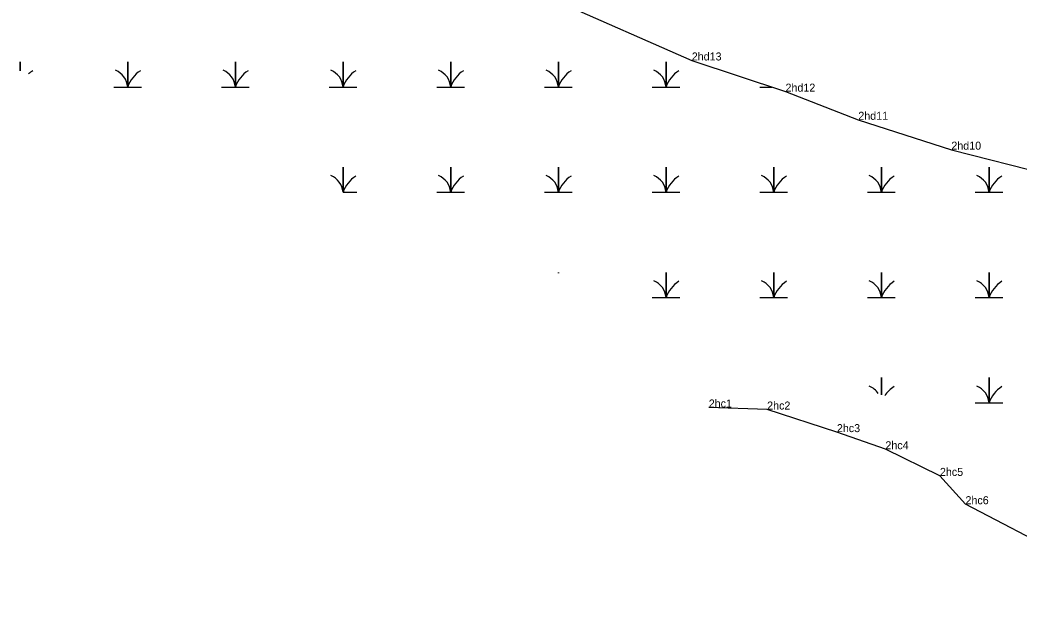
# Model space of a CAD drawing. Extents: x 2072529 to 2268796, y 436423 to 470406.
# Drawn here: x 2106175 to 2106799, y 453813 to 454182 of the extents above; entities that cross this region are included whole.
import ezdxf

# ---------------------------------------------------------------- set-up
doc = ezdxf.new("R2010")
doc.units = 0
for name, color, linetype in [('Exist Environmental Wetland Boundary Cogo Comment', 7, 'Continuous'), ('Exist Environmental Wetland Boundary Cogo Point CELL', 7, 'Continuous'), ('Old_Level_20', 7, 'Continuous')]:
    doc.layers.add(name, color=color, linetype=linetype)

msp = doc.modelspace()

# ---------------------------------------------------------------- linework, layer by layer
at = {"layer": 'Exist Environmental Wetland Boundary Cogo Point CELL'}
for points in [[(2106174.89, 454150.51), (2106174.89, 454156.11), (2106174.89, 454150.51)], [(2106233.53, 454140.33), (2106242.14, 454140.33), (2106242.14, 454156.11), (2106242.14, 454140.33), (2106250.74, 454140.33)], [(2106300.78, 454140.33), (2106309.39, 454140.33), (2106309.39, 454156.11), (2106309.39, 454140.33), (2106317.99, 454140.33)], [(2106368.03, 454140.33), (2106376.64, 454140.33), (2106376.64, 454156.11), (2106376.64, 454140.33), (2106385.24, 454140.33)], [(2106435.28, 454140.33), (2106443.89, 454140.33), (2106443.89, 454156.11), (2106443.89, 454140.33), (2106452.49, 454140.33)], [(2106502.53, 454140.33), (2106511.14, 454140.33), (2106511.14, 454156.11), (2106511.14, 454140.33), (2106519.74, 454140.33)], [(2106569.78, 454140.33), (2106578.39, 454140.33), (2106578.39, 454156.11), (2106578.39, 454140.33), (2106586.99, 454140.33)], [(2106637.03, 454140.33), (2106644.39, 454140.33)], [(2106376.64, 454074.58), (2106376.64, 454090.31), (2106376.64, 454074.58)], [(2106435.28, 454074.53), (2106443.89, 454074.53), (2106443.89, 454090.31), (2106443.89, 454074.53), (2106452.49, 454074.53)], [(2106502.53, 454074.53), (2106511.14, 454074.53), (2106511.14, 454090.31), (2106511.14, 454074.53), (2106519.74, 454074.53)], [(2106569.78, 454074.53), (2106578.39, 454074.53), (2106578.39, 454090.31), (2106578.39, 454074.53), (2106586.99, 454074.53)], [(2106637.03, 454074.53), (2106645.64, 454074.53), (2106645.64, 454090.31), (2106645.64, 454074.53), (2106654.24, 454074.53)], [(2106704.28, 454074.53), (2106712.89, 454074.53), (2106712.89, 454090.31), (2106712.89, 454074.53), (2106721.49, 454074.53)], [(2106771.53, 454074.53), (2106780.14, 454074.53), (2106780.14, 454090.31), (2106780.14, 454074.53), (2106788.74, 454074.53)], [(2106376.78, 454074.53), (2106385.24, 454074.53)], [(2106511.14, 454023.96), (2106511.14, 454024.51), (2106511.14, 454023.96)], [(2106569.78, 454008.73), (2106578.39, 454008.73), (2106578.39, 454024.51), (2106578.39, 454008.73), (2106586.99, 454008.73)], [(2106637.03, 454008.73), (2106645.64, 454008.73), (2106645.64, 454024.51), (2106645.64, 454008.73), (2106654.24, 454008.73)], [(2106704.28, 454008.73), (2106712.89, 454008.73), (2106712.89, 454024.51), (2106712.89, 454008.73), (2106721.49, 454008.73)], [(2106771.53, 454008.73), (2106780.14, 454008.73), (2106780.14, 454024.51), (2106780.14, 454008.73), (2106788.74, 454008.73)], [(2106712.89, 453948.03), (2106712.89, 453958.71), (2106712.89, 453948.03)], [(2106771.53, 453942.93), (2106780.14, 453942.93), (2106780.14, 453958.71), (2106780.14, 453942.93), (2106788.74, 453942.93)]]:
    msp.add_lwpolyline(points, dxfattribs=at)
for centre, radius, start, end in [((2106193.13, 454134.26), 19.22, 122.12745, 132.19295), ((2106229.87, 454139.44), 12.3, 4.14034, 67.53497), ((2106260.38, 454134.26), 19.22, 122.12745, 161.62219), ((2106297.12, 454139.44), 12.3, 4.14034, 67.53497), ((2106327.63, 454134.26), 19.22, 122.12745, 161.62219), ((2106364.37, 454139.44), 12.3, 4.14034, 67.53497), ((2106394.88, 454134.26), 19.22, 122.12745, 161.62219), ((2106431.62, 454139.44), 12.3, 4.14034, 67.53497), ((2106462.13, 454134.26), 19.22, 122.12745, 161.62219), ((2106498.87, 454139.44), 12.3, 4.14034, 67.53497), ((2106529.38, 454134.26), 19.22, 122.12745, 161.62219), ((2106566.12, 454139.44), 12.3, 4.14034, 67.53497), ((2106596.63, 454134.26), 19.22, 122.12745, 161.62219), ((2106364.37, 454073.64), 12.3, 4.40505, 67.53497), ((2106431.62, 454073.64), 12.3, 4.14034, 67.53497), ((2106498.87, 454073.64), 12.3, 4.14034, 67.53497), ((2106566.12, 454073.64), 12.3, 4.14034, 67.53497), ((2106633.37, 454073.64), 12.3, 4.14034, 67.53497), ((2106700.62, 454073.64), 12.3, 4.14034, 67.53497), ((2106767.87, 454073.64), 12.3, 4.14034, 67.53497), ((2106394.88, 454068.46), 19.22, 122.12745, 161.46846), ((2106462.13, 454068.46), 19.22, 122.12745, 161.62219), ((2106529.38, 454068.46), 19.22, 122.12745, 161.62219), ((2106596.63, 454068.46), 19.22, 122.12745, 161.62219), ((2106663.88, 454068.46), 19.22, 122.12745, 161.62219), ((2106731.13, 454068.46), 19.22, 122.12745, 161.62219), ((2106798.38, 454068.46), 19.22, 122.12745, 161.62219), ((2106566.12, 454007.84), 12.3, 4.14034, 67.53497), ((2106596.63, 454002.66), 19.22, 122.12745, 161.62219), ((2106633.37, 454007.84), 12.3, 4.14034, 67.53497), ((2106663.88, 454002.66), 19.22, 122.12745, 161.62219), ((2106700.62, 454007.84), 12.3, 4.14034, 67.53497), ((2106731.13, 454002.66), 19.22, 122.12745, 161.62219), ((2106767.87, 454007.84), 12.3, 4.14034, 67.53497), ((2106798.38, 454002.66), 19.22, 122.12745, 161.62219), ((2106700.62, 453942.04), 12.3, 33.18148, 67.53497), ((2106731.13, 453936.86), 19.22, 122.12745, 147.30499), ((2106767.87, 453942.04), 12.3, 4.14034, 67.53497), ((2106798.38, 453936.86), 19.22, 122.12745, 161.62219)]:
    msp.add_arc(centre, radius, start, end, dxfattribs=at)
at = {"layer": 'Old_Level_20'}
for p, q in [((2106594.46, 454156.94), (2106594.46, 454156.94)), ((2106653.02, 454137.45), (2106653.02, 454137.45)), ((2106698.5, 454119.85), (2106698.5, 454119.85)), ((2106756.6, 454101.18), (2106756.6, 454101.18)), ((2106605.07, 453940.05), (2106605.07, 453940.05)), ((2106641.55, 453938.77), (2106641.55, 453938.77)), ((2106685.12, 453924.67), (2106685.12, 453924.67)), ((2106715.42, 453913.96), (2106715.42, 453913.96)), ((2106749.46, 453897.3), (2106749.46, 453897.3)), ((2106765.42, 453879.6), (2106765.42, 453879.6))]:
    msp.add_line(p, q, dxfattribs=at)
for points in [[(2106225.82, 454287.77), (2106335.08, 454245.31), (2106388.83, 454223.88), (2106440.81, 454219.04), (2106510.17, 454194.07), (2106594.46, 454156.94), (2106653.02, 454137.45), (2106698.5, 454119.85), (2106756.6, 454101.18), (2106817.34, 454085.64), (2106852.39, 454068.44), (2106873.69, 454065.6), (2106917.57, 454044.06), (2106999.1, 454017.23), (2107048.91, 454001.25), (2107052.03, 453978.75), (2107063.45, 453958.83), (2107056.1, 453930.45)], [(2107175.9, 453920.17), (2107141.9, 453928.29), (2107104.26, 453928.26), (2107094.68, 453905.35), (2107083.05, 453891.68), (2107056.7, 453883.25), (2107040.21, 453845.27), (2106990.6, 453814.72), (2106937.33, 453813.49), (2106882.67, 453831.84), (2106873.68, 453824.36), (2106826.94, 453847.47), (2106765.43, 453879.6), (2106749.46, 453897.3), (2106715.42, 453913.96), (2106685.12, 453924.67), (2106641.55, 453938.77), (2106605.07, 453940.05)]]:
    msp.add_lwpolyline(points, dxfattribs=at)

# ---------------------------------------------------------------- texts
at = {"layer": 'Exist Environmental Wetland Boundary Cogo Comment'}
for s, p in [('2hd13', (2106594.46, 454156.94)), ('2hd12', (2106653.02, 454137.45)), ('2hd11', (2106698.5, 454119.85)), ('2hd10', (2106756.6, 454101.18)), ('2hc1', (2106605.07, 453940.05)), ('2hc2', (2106641.55, 453938.77)), ('2hc3', (2106685.12, 453924.67)), ('2hc4', (2106715.42, 453913.96)), ('2hc5', (2106749.46, 453897.3)), ('2hc6', (2106765.43, 453879.6))]:
    msp.add_text(s, height=5, dxfattribs=at).set_placement(p)

doc.saveas('drawing.dxf')
